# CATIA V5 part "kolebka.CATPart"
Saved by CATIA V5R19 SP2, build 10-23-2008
Part number: kolebka
Bounding box of the stored display mesh (mm): x -580 to 1160, y -1200 to 1200, z -150 to 339.888
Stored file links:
  C:\Users\Martiin\Desktop\9.semestr\Projekt-diplomka\3D model\kolebka.CATPart
  C:\Program Files\Dassault Systemes\B19\intel_a\reffiles\standard\MetricThinPitch.txt
  E:\Catia\intel_a\startup\materials\Catalog.CATMaterial
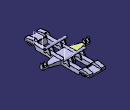
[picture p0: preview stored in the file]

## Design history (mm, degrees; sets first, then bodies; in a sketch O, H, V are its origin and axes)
WSupportSet1
Body1 (main body)
  Sketch1 on yz-plane, origin (0, 0, 0), H (0, 1, 0), V (0, 0, 1)
    construction line L1 (0, 482.4405) -> (0, -98.2488)
    point P1 (0, 482.4405)
    line L2 (0, 0) -> (-793.603, 0)
    point P3 (-793.603, 0)
    line L3 (-793.603, 0) -> (-830, 100)
    point P4 (-830, 100)
    line L4 (-830, 100) -> (-1200, 100)
    point P5 (-1200, 100)
    line L5 (-1200, 100) -> (-1200, 150)
    point P6 (-1200, 150)
    line L6 (-1200, 150) -> (0, 150)
    point P7 (0, 150)
    line L7 (0, 150) -> (0, 150)
    point P8 (0, 150)
    point P9 (0, 150)
    point P10 (793.603, 0)
    point P11 (830, 100)
    point P12 (1200, 100)
    point P13 (1200, 150)
    point P14 (0, 150)
    point P15 (0, 150)
    line L8 (793.603, 0) -> (830, 100)
    line L9 (830, 100) -> (1200, 100)
    line L10 (1200, 100) -> (1200, 150)
    line L11 (1200, 150) -> (0, 150)
    line L12 (0, 150) -> (0, 150)
    point P16 (0, 150)
    line L13 (0, 150) -> (0, 150)
    point P17 (0, 0)
    line L14 (0, 0) -> (793.603, 0)
    line L15 (-755.7735, 140) -> (-755.7735, 140)
    line L16 (755.7735, 140) -> (755.7735, 140)
    distance L5 L1 = 1200
    distance L4 L6 = 50
    distance L2 L4 = 100
    angle L2 L3 = 110
    distance P4 L5 = 370
    coincidence: P1 V, P9 L1, O P17, P9 P16, P7 P9
    vertical: L1 V, L5 V
    horizontal: L2 H, L4 H, L6 H
    symmetry: P3 P10 L1, P4 P11 L1, P5 P12 L1, P6 P13 L1, P7 P14 L1, P8 P15 L1, L3 L8 L1, L4 L9 L1, L5 L10 L1, L6 L11 L1, L7 L12 L1, P9 P16 L1, O P17 L1, L2 L14 L1
  Pad1: profile Sketch1, direction (1, 0, 0), length 140
  Shell1: IntOffset 10, Face face of Pad1 from Sketch1.L11, ExtOffset 0
  Sketch2 on face of Shell1, origin (0, -1190, 0), H (-1, 0, 0), V (0, 0, 1)
    line L1 (-130, 150) -> (-10, 150)
    line L2 (-10, 150) -> (-10, 140)
    line L3 (-10, 140) -> (-130, 140)
    line L4 (-130, 140) -> (-130, 150)
    reference projected line E1 (-130, 150) -> (-130, 110) from edge [face of Shell1 | face of Shell1]
    reference projected line E2 (-10, 150) -> (-190, 150) from edge [face of Pad1 from Sketch1.L6 | face of Shell1]
    reference projected line E3 (-10, 150) -> (-10, 110) from edge [face of Shell1 | face of Shell1]
    distance L3 L1 = 10
    horizontal: L1 H, L3 H
    vertical: L2 V, L4 V
    coincidence: E1 L4, L1 E2, E3 L2
  Pad2: profile Sketch2, direction (0, 1, 0), up to the existing solid (limit type 2)
  Sketch3 on end face of Pad1, origin (140, 0, 0), H (0, 1, 0), V (0, 0, 1)
    line L1 (-1200, 150) -> (-800, 150)
    point P2 (-800, 150)
    line L2 (-800, 150) -> (-918.6997, 249.6008)
    line L3 (-918.6997, 249.6008) -> (-1200, 200)
    point P4 (-1200, 200)
    line L4 (-1200, 200) -> (-1200, 150)
    reference projected line E1 (-1200, 150) -> (-1200, 100) from edge [face of Pad1 from Sketch1.L5 | end face of Pad1]
    reference projected line E2 (0, 150) -> (-1200, 150) from edge [face of Pad1 from Sketch1.L6 | end face of Pad1]
    angle L4 L3 = 100
    distance P2 L4 = 400
    angle L2 L1 = 40
    distance P4 L1 = 50
    horizontal: L1 H
    vertical: L4 V
    coincidence: E1 L4, L1 E2
  Pad3: profile Sketch3, direction (-1, 0, 0), length 10
  Sketch4 on end face of Pad3, origin (130, 0, 0), H (0, -1, 0), V (0, 0, 1)
    line L1 (918.6997, 249.6008) -> (1200, 200)
    line L2 (1200, 200) -> (1200, 150)
    reference projected line E1 (753.4293, 278.7425) -> (1200, 200) from edge [end face of Pad3 | face of Pad3 from Sketch3.L3]
    reference projected line E2 (1200, 200) -> (1200, 150) from edge [end face of Pad3 | face of Pad3]
    line L3 (1200, 150) -> (1190, 150)
    point P3 (1190, 150)
    reference projected line E3 (1200, 150) -> (600, 150) from edge [end face of Pad3 | face of Pad2]
    line L4 (908.6997, 241.2098) -> (1190, 191.609)
    line L5 (1190, 191.609) -> (1190, 150)
    point P5 (1190, 150)
    line L6 (918.6997, 249.6008) -> (908.6997, 241.2098)
    reference projected line E4 (682.6352, 51.5192) -> (836.0645, 180.2617) from edge [end face of Pad3 | face of Pad3 from Sketch3.L2]
    distance L4 L1 = 10
    distance L5 L2 = 10
    vertical: L2 V
    coincidence: E1 L1, E2 L2, L3 E3, P5 P3, E4 L6
    horizontal: L3 H
  Pad4: profile Sketch4, direction (-1, 0, 0), length 130
  Sketch5 on face of Pad4, origin (0, 0, 0), H (0, -1, 0), V (0, 0, 1)
    line L1 (908.6997, 241.2098) -> (1190, 191.609)
    line L2 (1190, 191.609) -> (1190, 150)
    line L3 (1190, 150) -> (800, 150)
    line L4 (800, 150) -> (908.6997, 241.2098)
    reference projected line E1 (-1200, 150) -> (1200, 150) from edge [face of Pad4 | face of Pad2]
    reference projected line E2 (1190, 191.609) -> (1190, 150) from edge [face of Pad4 from Sketch4.L5 | face of Pad4]
    reference projected line E3 (743.4293, 270.3515) -> (1190, 191.609) from edge [face of Pad4 from Sketch4.L4 | end face of Pad4]
    reference projected line E4 (741.3176, 100.7596) -> (877.3821, 214.9313) from edge [end face of Pad3 | face of Pad4]
    vertical: L2 V
    horizontal: L3 H
    coincidence: L3 E1, L2 E2, L1 E3, L4 E4
  Pad5: profile Sketch5, direction (1, 0, 0), length 10
  Point1: type Between, FirstPoint vertex [face of Pad4 | face of Pad1 from Sketch1.L4 | face of Pad3], SecondPoint vertex [face of Pad1 from Sketch1.L10 | face of Pad1 from Sketch1.L9 | face of Pad3], Ratio 0.5
  Plane1: type 3Points, Element1 Point1, Element2 vertex [face of Pad1 from Sketch1.L2 | face of Pad1 from Sketch1.L14 | face of Pad3], Element3 vertex [face of Pad1 from Sketch1.L14 | face of Pad5 | face of Pad1 from Sketch1.L2]
  Mirror1: of Pad3, Pad4, Pad5, about Plane1
  Sketch6 on face of Mirror1, origin (140, 0, 0), H (0, 1, 0), V (0, 0, 1)
    line L1 (-793.603, 0) -> (-830, 100)
    line L2 (-850, 184.1876) -> (-782.9612, 0)
    line L3 (-793.603, 0) -> (-782.9612, 0)
    reference projected line E1 (-763.603, 0) -> (0, 0) from edge [face of Pad1 from Sketch1.L2 | end face of Pad1]
    line L4 (-880, 150) -> (-1200, 150)
    line L5 (-1200, 150) -> (-1200, 100)
    line L6 (-1200, 100) -> (-830, 100)
    reference projected line E2 (-1200, 150) -> (-1200, 100) from edge [face of Pad4 | face of Mirror1]
    line L7 (-850, 184.1876) -> (-850, 170)
    line L8 (-850, 170) -> (-880, 170)
    line L9 (-880, 170) -> (-880, 150)
    reference projected line E3 (-1200, 150) -> (-1200, 100) from edge [face of Pad4 | face of Mirror1]
    reference projected line E4 (-830, 100) -> (-793.603, 0) from edge [face of Pad1 from Sketch1.L3 | end face of Pad1]
    distance L1 L2 = 10
    distance L4 L6 = 50
    distance L3 L4 = 150
    distance L8 L3 = 170
    distance L9 L7 = 30
    distance L7 E3 = 350
    coincidence: L3 E1, L5 E2, E4 L1
    horizontal: L4 H, L6 H, L8 H
    vertical: L5 V, L7 V, L9 V
  Pad6: profile Sketch6, direction (1, 0, 0), length 150
  Mirror2: of the body so far, about Plane1
  Plane2: type Offset, RefPlane end face of Pad6, Offset 0, reversed
  Mirror3: of the body so far, about Plane2
  Sketch7 on face of Mirror2, origin (0, 0, 0), H (0, -1, 0), V (0, 0, 1)
    point P1 (-350, 400)
    line L1 (-389.5447, 293.982) -> (-480, 100)
    point P2 (-480, 100)
    line L2 (-480, 100) -> (-420.3982, 100)
    point P3 (-220, 100)
    line L3 (-220, 100) -> (-310.4553, 293.982)
    construction line L4 (-350, 454.1532) -> (-350, 189.8921)
    point P6 (-350, 300)
    reference projected line E1 (0, 0) -> (-763.603, 0) from edge [face of Mirror2 | face of Pad1]
    arc A1 centre (-350, 300) radius 40 from (-389.5447, 293.982) to (-310.4553, 293.982) ccw
    point P9 (-355.3633, 339.6388)
    arc A2 centre (-350, 52.365) radius 85 from (-279.6018, 100) to (-420.3982, 100) ccw
    point P10 (-350, 52.365)
    line L5 (-279.6018, 100) -> (-220, 100)
    distance P6 P1 = 100
    angle L3 L2 = 65
    angle L1 L2 = 65
    distance L2 P6 = 200
    length L4 = 264.2612
    distance P3 L4 = 130
    distance P2 L4 = 130
    distance P6 V = 350
    distance L2 E1 = 100
    radius A1 = 40
    radius A2 = 85
    horizontal: L2 H, L5 H
    vertical: L4 V
    coincidence: P1 L4, P6 L4, A1 P9, P10 L4, L2 L5
  Pad7: profile Sketch7, direction (-1, 0, 0), length 15
  Pad8: profile start face of Pad7, direction along start face of Pad7, length 15
  Plane3: type Offset, RefPlane face of Mirror2, Offset 70
  Mirror4: of Pad7, Pad8, about Plane3
  Mirror5: of the body so far, about Plane2
  Mirror6: of the body so far, about Plane1
  Plane4: type Offset, RefPlane end face of Pad7, Offset 90, reversed
  Sketch8 on Plane4, origin (-105, 0, 0), H (0, 1, 0), V (0, 0, 1)
    circle A1 centre (350, 300) radius 40
    reference projected arc E1 centre (350, 300) radius 40 from (310.4553, 293.982) to (389.5447, 293.982) ccw from edge [face of Pad8 | end face of Pad7]
    circle A2 centre (350, 300) radius 30
    radius A1 = 40
    radius A2 = 30
    concentricity: E1 A1
  Pad9: profile Sketch8, direction (1, 0, 0), length 790
  Mirror7: of Pad9, about Plane1
  Plane5: type Offset, RefPlane face of Mirror6, Offset 400, reversed
  Sketch9 on Plane5, origin (-400, 0, 0), H (0, 1, 0), V (0, 0, 1)
    line L1 (60, 130) -> (-60, 130)
    line L2 (-60, 130) -> (-60, 60)
    line L3 (-60, 60) -> (60, 60)
    line L4 (60, 60) -> (60, 130)
    reference projected line E1 (0, 0) -> (-763.603, 0) from edge [face of Mirror6 | face of Mirror6]
    distance V L4 = 60
    distance L2 L4 = 120
    distance L3 L1 = 70
    distance L3 E1 = 60
    horizontal: L1 H, L3 H
    vertical: L2 V, L4 V
  Sketch10 on face of Mirror6, origin (0, 0, 0), H (0, -1, 0), V (0, 0, 1)
    line L1 (-150, 150) -> (150, 150)
    line L2 (150, 150) -> (150, 0)
    line L3 (150, 0) -> (-150, 0)
    line L4 (-150, 0) -> (-150, 150)
    reference projected line E1 (-600, 150) -> (600, 150) from edge [face of Mirror6 | face of Mirror6]
    reference projected line E2 (0, 0) -> (763.603, 0) from edge [face of Mirror6 | face of Mirror6]
    distance V L2 = 150
    distance L4 L2 = 300
    horizontal: L1 H, L3 H
    vertical: L2 V, L4 V
    coincidence: L1 E1, L3 E2
  Line1: type PtPt, FirstPoint vertex [element of Sketch10 | element of Sketch10], SecondPoint vertex [element of Sketch9 | element of Sketch9]
  Line2: type PtPt, FirstPoint vertex [element of Sketch10 | element of Sketch10], SecondPoint vertex [element of Sketch9 | element of Sketch9]
  Line3: type PtPt, FirstPoint vertex [element of Sketch10 | element of Sketch10], SecondPoint vertex [element of Sketch9 | element of Sketch9]
  Line4: type PtPt, FirstPoint vertex [element of Sketch10 | element of Sketch10], SecondPoint vertex [element of Sketch9 | element of Sketch9]
  Loft1: Sections (Sketch9; Sketch10), Guides (Line4; Line1; Line2; Line3)
  ThickSurface1: Surface Loft1, TopOffset 10, BotOffset 0
  Pad10: profile Sketch9, direction (1, 0, 0), length 10
  Pad11: profile Sketch9, direction (-1, 0, 0), length 180
  Sketch11 on end face of Pad11, origin (-580, 0, 0), H (0, -1, 0), V (0, 0, 1)
    line L1 (-60, 130) -> (-60, 180)
    line L2 (-60, 180) -> (-10, 180)
    line L3 (-10, 180) -> (-10, 240)
    line L4 (-10, 240) -> (40, 240)
    line L5 (40, 240) -> (40, 130)
    line L6 (40, 130) -> (-60, 130)
    reference projected line E1 (-60, 130) -> (60, 130) from edge [end face of Pad11 | face of Pad11 from Sketch9.L1]
    reference projected line E2 (-60, 60) -> (-60, 110) from edge [end face of Pad11 | face of Pad11 from Sketch9.L4]
    distance L4 L6 = 110
    distance L3 L5 = 50
    distance L1 L5 = 100
    distance L2 L6 = 50
    vertical: L1 V, L3 V, L5 V
    horizontal: L2 H, L4 H, L6 H
    coincidence: L6 E1, L1 E2
  Pad12: profile Sketch11, direction (1, 0, 0), length 40
  Sketch12 on face of Pad12, origin (-550.9714, 60, 134.6635), H (1, 0, 0), V (0, 0, -1)
    point P1 (-9.0286, -30.3365)
    reference projected line E1 (-29.0286, 74.6635) -> (-29.0286, 24.6635) from edge [face of Pad12 | face of Pad12]
    reference projected line E2 (-19.0286, -45.3365) -> (20.9714, -45.3365) from edge [face of Pad12 from Sketch11.L2 | face of Pad12]
    distance P1 E1 = 20
    distance P1 E2 = 15
  Hole1: placed by Sketch12, at (-560, 60, 165) direction (0, -1, 0), diameter 21, depth 40
  Sketch13 on face of Pad12 from Sketch11.L5, origin (-556.5787, -40, 161.0038), H (1, 0, 0), V (0, 0, 1)
    point P1 (-3.4213, 53.9962)
    reference projected line E1 (-23.4213, -51.0038) -> (-23.4213, 18.9962) from edge [face of Pad12 from Sketch11.L5 | face of Pad12]
    reference projected line E2 (-13.4213, 78.9962) -> (26.5787, 78.9962) from edge [face of Pad12 from Sketch11.L5 | face of Pad12 from Sketch11.L4]
    distance P1 E1 = 20
    distance P1 E2 = 25
  Hole2: placed by Sketch13, at (-560, -40, 215) direction (0, 1, 0), diameter 21, depth 40
  RectPattern1: of Pad12, Hole1, Hole2, direction 1 instances 2, spacing 135, along edge [face of Pad12 from Sketch11.L5 | face of Pad12 from Sketch11.L4], direction 2 instances 2, spacing 0
  Mirror8: of the body so far, about Plane2
  Sketch14 on face of Mirror8, origin (0, 0, 150), H (1, 0, 0), V (0, 1, 0)
    line L1 (120, 200) -> (460, 200)
    line L2 (460, 200) -> (460, -200)
    line L3 (460, -200) -> (120, -200)
    line L4 (120, -200) -> (120, 200)
    distance H L1 = 200
    distance L1 L3 = 400
    distance L4 V = 120
    distance L4 L2 = 340
    horizontal: L1 H, L3 H
    vertical: L2 V, L4 V
  Pad13: profile Sketch14, direction (0, 0, 1), length 10
  Pad14: profile start face of Pad13, direction along start face of Pad13, up to face of Mirror8
  Plane6: type Offset, RefPlane face of Mirror8, Offset 57.5, reversed
  Sketch15 on Plane6, origin (382.5, 0, 0), H (0, 1, 0), V (0, 0, 1)
    line L1 (300, 150) -> (200, 150)
    line L2 (200, 150) -> (200, -150)
    line L3 (200, -150) -> (300, -150)
    line L4 (300, -150) -> (300, 150)
    reference projected line E1 (456.6846, 150) -> (800, 150) from edge [face of Mirror8 | face of Mirror8]
    reference projected line E3 (200, 150) -> (200, 0) from edge [face of Mirror8 | face of Pad13]
    distance L1 L3 = 300
    distance L2 L4 = 100
    horizontal: L1 H, L3 H
    vertical: L2 V, L4 V
    coincidence: L1 E1, L2 E3
  Pad15: profile Sketch15, direction (-1, 0, 0), length 50
  Sketch16 on face of Pad15 from Sketch15.L3, origin (401.7508, 230.7369, -150), H (1, 0, 0), V (0, -1, 0)
    point P1 (-44.2508, -19.2631)
    reference projected line E1 (-69.2508, 30.7369) -> (-69.2508, -69.2631) from edge [end face of Pad15 | face of Pad15 from Sketch15.L3]
    reference projected line E2 (18.2492, 30.7369) -> (-31.7508, 30.7369) from edge [face of Pad15 from Sketch15.L2 | face of Pad15 from Sketch15.L3]
    distance P1 E1 = 25
    distance E2 P1 = 50
  Hole3: placed by Sketch16, at (357.5, 250, -150) direction (0, 0, 1), diameter 21, depth 40
  RectPattern2: of Pad15, direction 1 instances 2, spacing 500, along edge [face of Mirror8 | face of Mirror8] reversed, direction 2 instances 2, spacing 0
  RectPattern3: of Hole3, direction 1 instances 2, spacing 500, along edge [face of Mirror8 | face of Mirror8] reversed, direction 2 instances 2, spacing 0
  Mirror9: of the body so far, about Plane2
  Sketch17 on face of Mirror9, origin (197.5, 0, 0), H (0, -1, 0), V (0, 0, 1)
    line L1 (200, 150) -> (300, 50)
    point P1 (200, 150)
    line L2 (300, 50) -> (300, 150)
    line L3 (300, 150) -> (200, 150)
    reference projected line E1 (200, 150) -> (300, 150) from edge [face of Mirror9 | face of Mirror9]
    reference projected line E2 (300, 150) -> (300, -150) from edge [face of Mirror9 | face of Mirror9]
    reference projected point E3 (200, 150) from edge [face of Mirror9 | face of Mirror9]
    angle L1 L2 = 45
    horizontal: L3 H
    coincidence: L3 E1, L2 E2, P1 E3
  Pocket1: profile Sketch17, direction (1, 0, 0), up to face of RectPattern2
  Mirror10: of Pocket1, about Plane1
  Sketch18 on face of Mirror9, origin (0, 0, 100), H (1, 0, 0), V (0, -1, 0)
    arc A1 centre (40, 995) radius 100 from (0, 1086.6515) to (0, 903.3485) ccw
    point P1 (40, 995)
    reference intersected line E1 through (290, 0) direction (0, -1) from Plane2
    projected line E2 (0, 1200) -> (0, 830) from edge [face of Mirror9 | face of Mirror9]
    projected line E3 (0, 1086.6515) -> (0, 903.3485) from edge [face of Mirror9 | face of Mirror9]
    distance E1 P1 = 250
    radius A1 = 100
    distance H P1 = 995
  Pad16: profile Sketch18, direction (0, 0, 1), length 10
  Sketch19 on face of Mirror9, origin (0, 0, 100), H (1, 0, 0), V (0, -1, 0)
    circle A1 centre (40, 995) radius 60
    reference projected arc E1 centre (40, 995) radius 100 from (0, 1086.6515) to (0, 903.3485) ccw from edge [face of Pad16 from Sketch18.A1 | face of Pad16]
    radius A1 = 60
    concentricity: A1 E1
  Pad17: profile Sketch19, direction (0, 0, -1), length 20
  Mirror11: of Pad16, Pad17, about Plane2
  Mirror12: of the body so far, about Plane1
  Sketch20 on face of Mirror12, origin (0, 0, 130), H (1, 0, 0), V (0, 1, 0)
    line L1 (-540, 82.5368) -> (-445, 82.5368)
    line L2 (-445, 82.5368) -> (-445, -10)
    line L3 (-445, -10) -> (-540, -10)
    line L4 (-540, -10) -> (-540, 82.5368)
    reference projected line E1 (-445, 10) -> (-445, 60) from edge [face of Mirror9 | face of Mirror9]
    reference projected line E2 (-540, 10) -> (-540, 60) from edge [face of Mirror9 | face of Mirror9]
    reference projected line E3 (-400, 60) -> (-540, 60) from edge [face of Mirror9 | face of Mirror12]
    distance E3 L3 = 70
    horizontal: L1 H, L3 H
    vertical: L2 V, L4 V
    coincidence: L2 E1, L4 E2
  Pocket2: profile Sketch20, direction (0, 0, -1), length 20
  Sketch21 on face of Mirror12, origin (0, 0, 130), H (1, 0, 0), V (0, 1, 0)
    line L1 (1025, 10) -> (1120, 10)
    line L2 (1120, 10) -> (1120, -99.0601)
    line L3 (1120, -99.0601) -> (1025, -99.0601)
    line L4 (1025, -99.0601) -> (1025, 10)
    reference projected line E1 (1120, 10) -> (1120, -40) from edge [face of Mirror9 | face of Mirror9]
    reference projected line E2 (1025, -40) -> (1025, 10) from edge [face of Mirror9 | face of Mirror9]
    reference projected line E3 (985, -60) -> (980, -60) from edge [face of Mirror12 | face of Mirror12]
    distance L1 E3 = 70
    horizontal: L1 H, L3 H
    vertical: L2 V, L4 V
    coincidence: L2 E1, L4 E2
  Pocket3: profile Sketch21, direction (0, 0, -1), length 20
